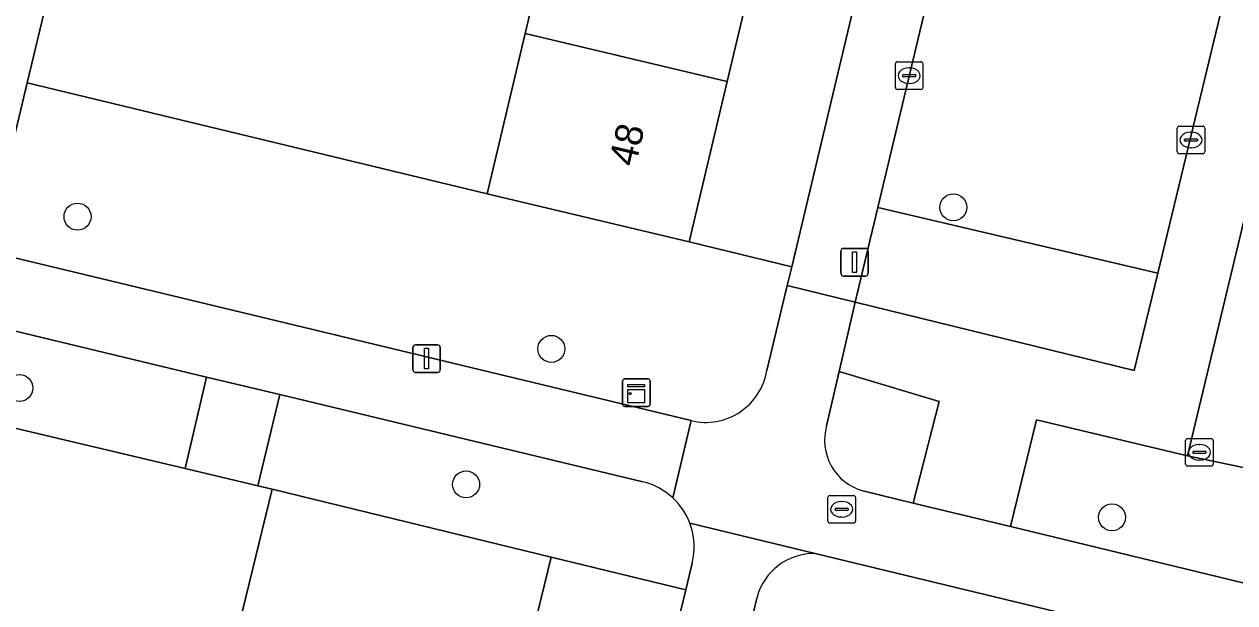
# Model space of a CAD drawing. Extents: x 162803 to 163818, y 381639 to 382475.
# Drawn here: x 163227.45 to 163271.29, y 382172.97 to 382193.93 of the extents above; entities that cross this region are included whole.
import ezdxf

# ---------------------------------------------------------------- set-up
doc = ezdxf.new("R2010")
doc.units = 0
for name, color, linetype in [('IMGEO_Boom', 7, 'Continuous'), ('IMGEO_Erf', 7, 'Continuous'), ('IMGEO_Groenvoorziening', 7, 'Continuous'), ('IMGEO_Hek', 7, 'Continuous'), ('IMGEO_Kast', 7, 'Continuous'), ('IMGEO_Kolk', 7, 'Continuous'), ('IMGEO_Lichtmast', 7, 'Continuous'), ('IMGEO_Pand', 7, 'Continuous'), ('IMGEO_Pand_nummerreeks', 7, 'Continuous'), ('IMGEO_Rioolput', 7, 'Continuous'), ('IMGEO_Voetpad_open', 7, 'Continuous')]:
    doc.layers.add(name, color=color, linetype=linetype)

msp = doc.modelspace()

# ---------------------------------------------------------------- linework, layer by layer
at = {"layer": 'IMGEO_Boom'}
for centre in [(163261.099, 382187.294), (163229.379, 382186.953), (163246.542, 382182.164), (163227.275, 382180.747), (163243.453, 382177.253), (163266.844, 382176.062)]:
    msp.add_circle(centre, 0.489, dxfattribs=at)
at = {"layer": 'IMGEO_Erf'}
msp.add_lwpolyline([(163269.065, 382243.217), (163265.32, 382244.147), (163263.897, 382238.151), (163262.521, 382232.348), (163261.145, 382226.549), (163259.768, 382220.747), (163258.418, 382215.054), (163257.074, 382209.393), (163255.687, 382203.543), (163254.229, 382197.399), (163252.912, 382191.849), (163251.535, 382186.045), (163255.248, 382185.136)], close=True, dxfattribs=at)
for points in [[(163228.322, 382194.981), (163227.554, 382191.804), (163244.218, 382187.781), (163245.595, 382193.585), (163246.912, 382199.135)], [(163234.884, 382170.738), (163236.429, 382177.084), (163235.909, 382177.207), (163233.273, 382177.831), (163221.704, 382180.57)], [(163245.275, 382148.098), (163251.41, 382173.436), (163246.536, 382174.624), (163244.992, 382168.279)]]:
    msp.add_lwpolyline(points, dxfattribs=at)
at = {"layer": 'IMGEO_Groenvoorziening'}
for points in [[(163260.846, 382197.184), (163260.531, 382196.358), (163258.368, 382187.292), (163268.502, 382184.903), (163270.876, 382194.712)], [(163244.218, 382187.781), (163227.554, 382191.804), (163226.098, 382185.706), (163251.602, 382179.565)], [(163254.34, 382181.376), (163255.086, 382184.466), (163255.248, 382185.136), (163251.535, 382186.045), (163244.218, 382187.781)], [(163257.82, 382177.025), (163259.647, 382176.573), (163260.581, 382180.263), (163256.959, 382181.347), (163256.51, 382179.379)], [(163249.848, 382177.351), (163236.703, 382180.508), (163235.909, 382177.207), (163236.429, 382177.084), (163239.399, 382176.361), (163246.536, 382174.624), (163251.41, 382173.436), (163251.645, 382174.406)], [(163266.24, 382172.299), (163256.094, 382174.749)], [(163253.994, 382173.174), (163253.909, 382172.83), (163253.354, 382170.579)]]:
    msp.add_lwpolyline(points, dxfattribs=at)
for points in [[(163272.811, 382181.055), (163275.427, 382191.863), (163272.912, 382192.189), (163269.579, 382178.285), (163272.171, 382177.751), (163272.792, 382180.266), (163272.627, 382180.291)], [(163268.502, 382184.903), (163258.368, 382187.292), (163257.549, 382183.861), (163267.649, 382181.378)], [(163234.051, 382181.144), (163222.418, 382183.938), (163221.704, 382180.57), (163233.273, 382177.831)], [(163296.089, 382167.75), (163297.042, 382171.68), (163272.171, 382177.751), (163269.579, 382178.285), (163264.11, 382179.591), (163263.175, 382175.728)]]:
    msp.add_lwpolyline(points, close=True, dxfattribs=at)
for centre, radius, start, end in [((163252.129, 382181.744), 2.242, 256.4121, 350.5517), ((163258.333, 382178.852), 1.898, 163.8796, 254.3122), ((163249.281, 382174.99), 2.429, 46.941, 76.4951), ((163249.267, 382174.975), 2.449, 20.8147, 46.9387), ((163249.269, 382174.981), 2.445, 346.3901, 20.6882), ((163256.056, 382172.612), 2.138, 88.9894, 164.7504)]:
    msp.add_arc(centre, radius, start, end, dxfattribs=at)
at = {"layer": 'IMGEO_Hek'}
msp.add_lwpolyline([(163227.554, 382191.804), (163244.218, 382187.781)], dxfattribs=at)
at = {"layer": 'IMGEO_Kast'}
for p, q in [((163249.119, 382180.155), (163249.119, 382180.996)), ((163249.119, 382180.996), (163249.119, 382180.155)), ((163249.194, 382181.08), (163250.035, 382181.08)), ((163250.035, 382181.08), (163249.194, 382181.08)), ((163250.119, 382181.005), (163250.119, 382180.164)), ((163250.119, 382180.164), (163250.119, 382181.005)), ((163250.044, 382180.08), (163249.203, 382180.08)), ((163249.203, 382180.08), (163250.044, 382180.08))]:
    msp.add_line(p, q, dxfattribs=at)
for points in [[(163249.314, 382180.87), (163249.914, 382180.87), (163249.914, 382180.785), (163249.314, 382180.785), (163249.314, 382180.87)], [(163249.314, 382180.695), (163249.914, 382180.695), (163249.914, 382180.206), (163249.314, 382180.206), (163249.314, 382180.695)]]:
    msp.add_lwpolyline(points, dxfattribs=at)
msp.add_circle((163249.398, 382180.544), 0.0377, dxfattribs=at)
for centre, start, end in [((163249.197, 382181.002), 92.4484, 184.2845), ((163249.197, 382181.002), 92.4484, 184.2845), ((163250.041, 382181.002), 2.4484, 94.2845), ((163250.041, 382181.002), 2.4484, 94.2845), ((163249.197, 382180.158), 182.4484, 274.2845), ((163249.197, 382180.158), 182.4484, 274.2845), ((163250.041, 382180.158), 272.4484, 4.2845), ((163250.041, 382180.158), 272.4484, 4.2845)]:
    msp.add_arc(centre, 0.0779, start, end, dxfattribs=at)
at = {"layer": 'IMGEO_Kolk'}
for p, q in [((163259.074, 382192.564), (163259.926, 382192.564)), ((163258.999, 382191.638), (163258.999, 382192.49)), ((163259.301, 382192.107), (163259.699, 382192.107)), ((163259.487, 382192.344), (163259.512, 382192.344)), ((163260, 382192.49), (163260, 382191.638)), ((163259.258, 382192.058), (163259.258, 382192.07)), ((163259.696, 382192.021), (163259.298, 382192.021)), ((163259.51, 382191.784), (163259.485, 382191.784)), ((163259.742, 382192.07), (163259.742, 382192.058)), ((163259.926, 382191.564), (163259.074, 382191.564)), ((163269.206, 382189.307), (163269.206, 382190.159)), ((163269.281, 382190.233), (163270.133, 382190.233)), ((163269.694, 382190.013), (163269.719, 382190.013)), ((163270.207, 382190.159), (163270.207, 382189.307)), ((163269.465, 382189.727), (163269.465, 382189.739)), ((163269.903, 382189.69), (163269.505, 382189.69)), ((163269.508, 382189.776), (163269.906, 382189.776)), ((163269.949, 382189.739), (163269.949, 382189.727)), ((163270.133, 382189.233), (163269.281, 382189.233)), ((163269.717, 382189.453), (163269.692, 382189.453))]:
    msp.add_line(p, q, dxfattribs=at)
for points in [[(163259.074, 382192.564), (163259.926, 382192.564)], [(163258.999, 382191.638), (163258.999, 382192.49)], [(163260, 382192.49), (163260, 382191.638)], [(163259.926, 382191.564), (163259.074, 382191.564)], [(163269.206, 382189.307), (163269.206, 382190.159)], [(163269.281, 382190.233), (163270.133, 382190.233)], [(163270.207, 382190.159), (163270.207, 382189.307)], [(163270.133, 382189.233), (163269.281, 382189.233)]]:
    msp.add_lwpolyline(points, dxfattribs=at)
for centre, radius, start, end in [((163259.076, 382192.488), 0.0765, 91.552, 178.448), ((163259.076, 382192.488), 0.0765, 91.552, 178.448), ((163259.924, 382192.488), 0.0765, 1.552, 88.448), ((163259.924, 382192.488), 0.0765, 1.552, 88.448), ((163259.298, 382192.067), 0.0403, 85.8775, 175.7526), ((163259.703, 382192.069), 0.0386, 1.7309, 96.639), ((163259.295, 382192.057), 0.0366, 178.938, 274.7102), ((163259.699, 382192.064), 0.043, 264.8664, 352.4533), ((163259.076, 382191.64), 0.0765, 181.552, 268.448), ((163259.076, 382191.64), 0.0765, 181.552, 268.448), ((163259.924, 382191.64), 0.0765, 271.552, 358.448), ((163259.924, 382191.64), 0.0765, 271.552, 358.448), ((163269.283, 382190.157), 0.0765, 91.552, 178.448), ((163269.283, 382190.157), 0.0765, 91.552, 178.448), ((163270.131, 382190.157), 0.0765, 1.552, 88.448), ((163270.131, 382190.157), 0.0765, 1.552, 88.448), ((163269.505, 382189.736), 0.0403, 85.8775, 175.7526), ((163269.502, 382189.726), 0.0366, 178.938, 274.7102), ((163269.906, 382189.733), 0.043, 264.8664, 352.4533), ((163269.91, 382189.738), 0.0386, 1.7309, 96.639), ((163269.283, 382189.309), 0.0765, 181.552, 268.448), ((163269.283, 382189.309), 0.0765, 181.552, 268.448), ((163270.131, 382189.309), 0.0765, 271.552, 358.448), ((163270.131, 382189.309), 0.0765, 271.552, 358.448)]:
    msp.add_arc(centre, radius, start, end, dxfattribs=at)
for centre, major_axis, ratio, start_param, end_param in [((163259.486, 382192.064), (-0.387, 0.002), 0.722429, 4.712389, 7.853982), ((163259.511, 382192.064), (-0.39, 0.002), 0.717154, 1.570796, 4.712389), ((163269.693, 382189.733), (-0.387, 0.002), 0.722429, 4.712389, 7.853982), ((163269.718, 382189.733), (-0.39, 0.002), 0.717154, 1.570796, 4.712389)]:
    msp.add_ellipse(centre, major_axis=major_axis, ratio=ratio, start_param=start_param, end_param=end_param, dxfattribs=at)
at = {"layer": 'IMGEO_Lichtmast'}
for p, q in [((163257.025, 382184.904), (163257.025, 382185.704)), ((163257.025, 382185.704), (163257.025, 382184.904)), ((163257.125, 382185.804), (163257.915, 382185.804)), ((163257.915, 382185.804), (163257.125, 382185.804)), ((163258.015, 382185.704), (163258.015, 382184.904)), ((163258.015, 382184.904), (163258.015, 382185.704)), ((163257.915, 382184.804), (163257.125, 382184.804)), ((163257.125, 382184.804), (163257.915, 382184.804)), ((163241.526, 382181.411), (163241.526, 382182.211)), ((163241.526, 382182.211), (163241.526, 382181.411)), ((163241.626, 382182.311), (163242.416, 382182.311)), ((163242.416, 382182.311), (163241.626, 382182.311)), ((163242.516, 382182.211), (163242.516, 382181.411)), ((163242.516, 382181.411), (163242.516, 382182.211)), ((163242.416, 382181.311), (163241.626, 382181.311)), ((163241.626, 382181.311), (163242.416, 382181.311))]:
    msp.add_line(p, q, dxfattribs=at)
for points in [[(163257.445, 382185.679), (163257.595, 382185.679), (163257.595, 382184.929), (163257.445, 382184.929), (163257.445, 382185.679)], [(163241.946, 382182.186), (163242.096, 382182.186), (163242.096, 382181.436), (163241.946, 382181.436), (163241.946, 382182.186)]]:
    msp.add_lwpolyline(points, dxfattribs=at)
for centre, start, end in [((163257.125, 382185.704), 90, 180), ((163257.125, 382185.704), 90, 180), ((163257.915, 382185.704), 0, 90), ((163257.915, 382185.704), 360, 90), ((163257.125, 382184.904), 180, 270), ((163257.125, 382184.904), 180, 270), ((163257.915, 382184.904), 270, 0), ((163257.915, 382184.904), 270, 0), ((163241.626, 382182.211), 90, 180), ((163241.626, 382182.211), 90, 180), ((163242.416, 382182.211), 0, 90), ((163242.416, 382182.211), 360, 90), ((163241.626, 382181.411), 180, 270), ((163241.626, 382181.411), 180, 270), ((163242.416, 382181.411), 270, 0), ((163242.416, 382181.411), 270, 0)]:
    msp.add_arc(centre, 0.1, start, end, dxfattribs=at)
at = {"layer": 'IMGEO_Pand'}
for points in [[(163252.912, 382191.849), (163254.229, 382197.399), (163246.912, 382199.135), (163245.595, 382193.585)], [(163245.595, 382193.585), (163244.218, 382187.781), (163251.535, 382186.045), (163252.912, 382191.849)], [(163244.992, 382168.279), (163246.536, 382174.624), (163239.399, 382176.361), (163236.429, 382177.084), (163234.884, 382170.738), (163235.375, 382170.618)]]:
    msp.add_lwpolyline(points, close=True, dxfattribs=at)
at = {"layer": 'IMGEO_Rioolput'}
for p, q in [((163269.51, 382177.991), (163269.51, 382178.843)), ((163269.585, 382178.917), (163270.437, 382178.917)), ((163269.998, 382178.697), (163270.023, 382178.697)), ((163270.511, 382178.843), (163270.511, 382177.991)), ((163269.769, 382178.411), (163269.769, 382178.423)), ((163270.207, 382178.374), (163269.809, 382178.374)), ((163269.812, 382178.46), (163270.21, 382178.46)), ((163270.021, 382178.137), (163269.996, 382178.137)), ((163270.253, 382178.423), (163270.253, 382178.411)), ((163270.437, 382177.917), (163269.585, 382177.917)), ((163256.555, 382175.927), (163256.555, 382176.779)), ((163256.63, 382176.853), (163257.482, 382176.853)), ((163257.556, 382176.779), (163257.556, 382175.927)), ((163256.814, 382176.347), (163256.814, 382176.359)), ((163256.857, 382176.396), (163257.255, 382176.396)), ((163257.043, 382176.633), (163257.068, 382176.633)), ((163257.298, 382176.359), (163257.298, 382176.347)), ((163257.252, 382176.31), (163256.854, 382176.31)), ((163257.066, 382176.073), (163257.041, 382176.073)), ((163257.482, 382175.853), (163256.63, 382175.853))]:
    msp.add_line(p, q, dxfattribs=at)
for points in [[(163269.51, 382177.991), (163269.51, 382178.843)], [(163269.585, 382178.917), (163270.437, 382178.917)], [(163270.511, 382178.843), (163270.511, 382177.991)], [(163270.437, 382177.917), (163269.585, 382177.917)], [(163256.555, 382175.927), (163256.555, 382176.779)], [(163256.63, 382176.853), (163257.482, 382176.853)], [(163257.556, 382176.779), (163257.556, 382175.927)], [(163257.482, 382175.853), (163256.63, 382175.853)]]:
    msp.add_lwpolyline(points, dxfattribs=at)
for centre, radius, start, end in [((163269.587, 382178.841), 0.0765, 91.552, 178.448), ((163269.587, 382178.841), 0.0765, 91.552, 178.448), ((163270.435, 382178.841), 0.0765, 1.552, 88.448), ((163270.435, 382178.841), 0.0765, 1.552, 88.448), ((163269.809, 382178.42), 0.0403, 85.8775, 175.7526), ((163269.806, 382178.41), 0.0366, 178.938, 274.7102), ((163270.21, 382178.417), 0.043, 264.8664, 352.4533), ((163270.214, 382178.422), 0.0386, 1.7309, 96.639), ((163269.587, 382177.993), 0.0765, 181.552, 268.448), ((163269.587, 382177.993), 0.0765, 181.552, 268.448), ((163270.435, 382177.993), 0.0765, 271.552, 358.448), ((163270.435, 382177.993), 0.0765, 271.552, 358.448), ((163256.632, 382176.777), 0.0765, 91.552, 178.448), ((163256.632, 382176.777), 0.0765, 91.552, 178.448), ((163257.48, 382176.777), 0.0765, 1.552, 88.448), ((163257.48, 382176.777), 0.0765, 1.552, 88.448), ((163256.854, 382176.356), 0.0403, 85.8775, 175.7526), ((163256.851, 382176.346), 0.0366, 178.938, 274.7102), ((163257.255, 382176.353), 0.043, 264.8664, 352.4533), ((163257.259, 382176.358), 0.0386, 1.7309, 96.639), ((163256.632, 382175.929), 0.0765, 181.552, 268.448), ((163256.632, 382175.929), 0.0765, 181.552, 268.448), ((163257.48, 382175.929), 0.0765, 271.552, 358.448), ((163257.48, 382175.929), 0.0765, 271.552, 358.448)]:
    msp.add_arc(centre, radius, start, end, dxfattribs=at)
for centre, major_axis, ratio, start_param, end_param in [((163269.997, 382178.417), (-0.387, 0.002), 0.722429, 4.712389, 7.853982), ((163270.022, 382178.417), (-0.39, 0.002), 0.717154, 1.570796, 4.712389), ((163257.042, 382176.353), (-0.387, 0.002), 0.722429, 4.712389, 7.853982), ((163257.067, 382176.353), (-0.39, 0.002), 0.717154, 1.570796, 4.712389)]:
    msp.add_ellipse(centre, major_axis=major_axis, ratio=ratio, start_param=start_param, end_param=end_param, dxfattribs=at)
at = {"layer": 'IMGEO_Voetpad_open'}
for points in [[(163269.474, 382244.937), (163269.065, 382243.217), (163255.248, 382185.136), (163255.086, 382184.466), (163257.549, 382183.861), (163258.368, 382187.292), (163260.531, 382196.358), (163260.846, 382197.184)], [(163270.876, 382194.712), (163268.502, 382184.903), (163267.649, 382181.378), (163257.549, 382183.861), (163256.959, 382181.347), (163260.581, 382180.263), (163259.647, 382176.573), (163263.175, 382175.728), (163264.11, 382179.591), (163269.579, 382178.285), (163272.912, 382192.189)], [(163195.134, 382193.161), (163194.519, 382190.638), (163220.872, 382184.309), (163222.418, 382183.938), (163234.051, 382181.144), (163236.703, 382180.508), (163249.848, 382177.351)], [(163250.939, 382176.764), (163251.602, 382179.565), (163226.098, 382185.706), (163224.627, 382186.06), (163195.134, 382193.161)], [(163256.51, 382179.379), (163256.959, 382181.347), (163257.549, 382183.861), (163255.086, 382184.466), (163254.34, 382181.376)], [(163251.602, 382179.565), (163250.939, 382176.764)], [(163296.089, 382167.75), (163263.175, 382175.728), (163259.647, 382176.573), (163257.82, 382177.025)], [(163256.094, 382174.749), (163251.556, 382175.845)], [(163251.556, 382175.845), (163256.094, 382174.749), (163266.24, 382172.299), (163269.156, 382171.595), (163275.374, 382170.094), (163280.096, 382168.954), (163295.227, 382165.323), (163333.95, 382155.997), (163337.772, 382155.076), (163338.36, 382157.513), (163314.355, 382163.32), (163310.813, 382164.181), (163296.089, 382167.75)], [(163251.645, 382174.406), (163251.41, 382173.436), (163245.275, 382148.098), (163244.795, 382145.935), (163248.834, 382144.735)], [(163253.354, 382170.579), (163253.909, 382172.83), (163253.994, 382173.174)]]:
    msp.add_lwpolyline(points, dxfattribs=at)
for points in [[(163231.285, 382206.902), (163231.72, 382209.229), (163232.231, 382211.964), (163232.641, 382211.887), (163233.791, 382216.637), (163232.379, 382216.987), (163225.485, 382189.73), (163224.627, 382186.06), (163226.098, 382185.706), (163227.554, 382191.804), (163228.322, 382194.981), (163228.929, 382197.539), (163229.532, 382200.08)], [(163236.703, 382180.508), (163234.051, 382181.144), (163233.273, 382177.831), (163235.909, 382177.207)]]:
    msp.add_lwpolyline(points, close=True, dxfattribs=at)
for centre, radius, start, end in [((163252.129, 382181.744), 2.242, 256.4121, 350.5517), ((163258.333, 382178.852), 1.898, 163.8796, 254.3122), ((163249.281, 382174.99), 2.429, 46.941, 76.4951), ((163249.267, 382174.975), 2.449, 20.8147, 46.9387), ((163249.269, 382174.981), 2.445, 346.3901, 20.6882), ((163256.056, 382172.612), 2.138, 88.9894, 164.7504)]:
    msp.add_arc(centre, radius, start, end, dxfattribs=at)

# ---------------------------------------------------------------- texts
at = {"layer": 'IMGEO_Pand_nummerreeks'}
msp.add_text('48', height=1, rotation=76.6531, dxfattribs=at).set_placement((163249.582, 382188.731))

doc.saveas('drawing.dxf')
